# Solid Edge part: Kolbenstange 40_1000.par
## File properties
Username: ahadarics
Dokumentum tartalom típus: 0
Author: ahadarics
Last saved by: ahadarics
Revision: 101
Sűrűség: 0,000 kg/m^3
Pontosság: 0,990
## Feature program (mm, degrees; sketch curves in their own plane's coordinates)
base feature "unnamed BaseFeature 1"
thread "unnamed Thread 1"
chamfer "Letörés_1"  SetBackValue2 = 20 deg
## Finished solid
Body 1: solid body, 21 faces, 32 edges, 14 vertices.
  Faces by surface: plane 8, cylinder 5, cone 4, torus 4
  Edges by curve: circle 17, line 9, curve on surface 4, ellipse 2
Bounding box of the edges (mm; curved faces can reach further): 40.000 x 40.000 x 1128.000, from (-20, -20, -78) to (20, 20, 1050).
Cylindrical faces by radius (mm): R5 x1, R6 x1, R7.75 x1, R8 x1, R20 x1
Conical faces (half-angle, radius in mm at the cone's reference point): 20 deg R6 x1, 30 deg R7.875 x1, 45 deg R19.6 x1, 60 deg R5.5 x1
Toroidal faces (ring radius, tube radius in mm): R5.4 r0.4 x2, R6.55 r1.2 x2
Planar faces by outward normal: +x 1, +z 3, -x 1, -z 1, oblique 2
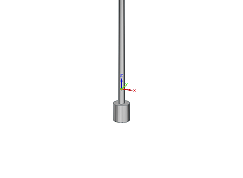
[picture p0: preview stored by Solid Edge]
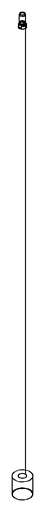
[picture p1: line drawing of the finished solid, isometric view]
